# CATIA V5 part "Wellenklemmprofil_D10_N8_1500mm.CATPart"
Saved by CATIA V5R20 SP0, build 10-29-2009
Part number: Wellenklemmprofil_D10_N8_X-Achse
Bounding box of the stored display mesh (mm): x 0 to 1420, y -9 to 9, z -12 to 15
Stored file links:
  C:\Users\Andi\Desktop\Offene Projekte\Plasmacutter\Rahmen\Wellenklemmprofil_D10_N8_1500mm.CATPart
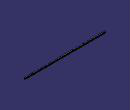
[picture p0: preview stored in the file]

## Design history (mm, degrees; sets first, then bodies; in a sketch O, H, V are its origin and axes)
Body1 (main body)
  Sketch1 on yz-plane, origin (0, 0, 0), H (0, 1, 0), V (0, 0, 1)
    line L1 (-9, 10) -> (-9, 0)
    point P2 (-9, 0)
    line L2 (-9, 0) -> (-4, 0)
    line L3 (-4, 0) -> (-4, -12)
    line L4 (-4, -12) -> (4, -12)
    line L5 (4, -12) -> (4, 0)
    point P6 (4, 0)
    line L6 (4, 0) -> (9, 0)
    line L7 (9, 0) -> (9, 10)
    line L8 (9, 10) -> (7.0993, 10)
    line L9 (-9, 10) -> (-7.0993, 10)
    arc A1 centre (0, 8) radius 7 from (-6.8075, 9.6301) to (6.8075, 9.6301) ccw
    point P9 (0, 8)
    arc A2 centre (-7.0993, 9.7) radius 0.3 from (-6.8075, 9.6301) to (-7.0993, 10) ccw
    arc A3 centre (7.0993, 9.7) radius 0.3 from (6.8075, 9.6301) to (7.0993, 10) cw
    radius A1 = 7
    distance L6 L8 = 10
    distance L7 L1 = 18
    radius A2 = 0.3
    radius A3 = 0.3 {= Sketch1.radius(A2)}
    distance P9 L6 = 8
    distance L8 L4 = 22
    distance L5 L3 = 8
    coincidence: P2 H, P6 H, P9 V, L9 L8
    vertical: L1 V, L3 V, L5 V, L7 V
    horizontal: L2 H, L4 H, L6 H, L8 H, L9 H
    symmetry: L7 L1 V, L3 L5 V
    tangency: A2 A1, A2 L9, A3 A1, A3 L8
  Pad1: profile Sketch1, direction (1, 0, 0), length 1420
  Fillet1: radius 0.3, on edge [face of Pad1 from Sketch1.L8 | face of Pad1 from Sketch1.L7]; edge [face of Pad1 from Sketch1.L1 | face of Pad1 from Sketch1.L9]
Body2
  Sketch2 on yz-plane, origin (0, 0, 0), H (0, 1, 0), V (0, 0, 1)
    circle A1 centre (0, 8) radius 7
    reference projected arc E1 centre (0, 8) radius 7 from (-6.8182, 9.5849) to (6.8182, 9.5849) ccw from edge [face of Pad1 from Sketch1.A1 | end face of Pad1]
    coincidence: A1 E1
  Pad2: profile Sketch2, direction (1, 0, 0), length 1420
